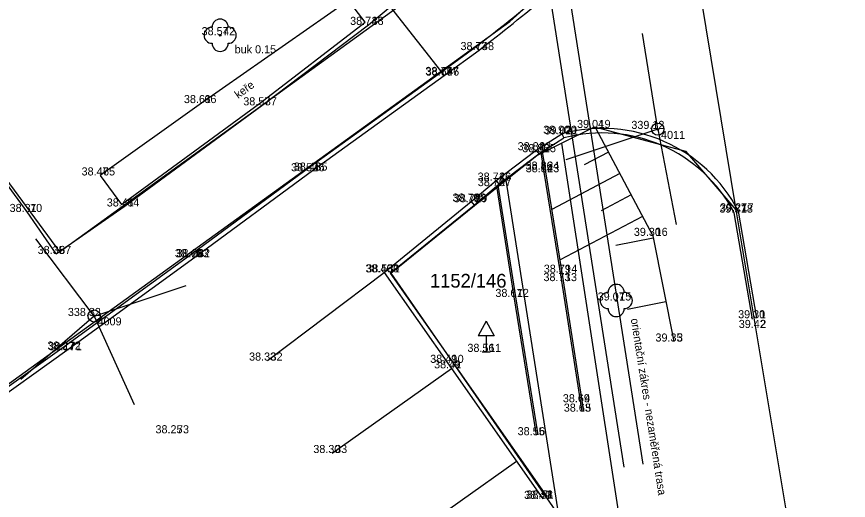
# Model space of a CAD drawing. Extents: x -609709 to -609357, y -1051535 to -1051131.
# Drawn here: x -609522.67 to -609496.91, y -1051331.13 to -1051316.16 of the extents above; entities that cross this region are included whole.
import ezdxf

# ---------------------------------------------------------------- set-up
doc = ezdxf.new("R2010")
doc.units = 0
for name, color, linetype in [('Vrstva 1', 7, 'Continuous'), ('Vrstva 10', 7, 'Continuous'), ('Vrstva 18', 7, 'Continuous'), ('Vrstva 19', 7, 'Continuous'), ('Vrstva 2', 7, 'Continuous'), ('Vrstva 3', 7, 'Continuous'), ('Vrstva 4', 7, 'Continuous'), ('Vrstva 5', 7, 'Continuous'), ('Vrstva 6', 7, 'Continuous'), ('Vrstva 7', 7, 'Continuous'), ('Vrstva 8', 7, 'Continuous')]:
    doc.layers.add(name, color=color, linetype=linetype)

msp = doc.modelspace()

# ---------------------------------------------------------------- linework, layer by layer
at = {"layer": 'Vrstva 1'}
for p, q in [((-609511.77, -1051316.42), (-609511.77, -1051316.42)), ((-609516.37, -1051316.74), (-609516.37, -1051316.74)), ((-609508.35, -1051317.2), (-609508.35, -1051317.2)), ((-609509.44, -1051317.97), (-609509.44, -1051317.97)), ((-609509.43, -1051317.99), (-609509.43, -1051317.99)), ((-609516.95, -1051318.84), (-609516.95, -1051318.84)), ((-609515.08, -1051318.91), (-609515.08, -1051318.91)), ((-609504.74, -1051319.61), (-609504.74, -1051319.61)), ((-609502.81, -1051319.65), (-609502.81, -1051319.65)), ((-609505.78, -1051319.79), (-609505.78, -1051319.79)), ((-609505.75, -1051319.81), (-609505.75, -1051319.81)), ((-609506.58, -1051320.3), (-609506.58, -1051320.3)), ((-609506.43, -1051320.36), (-609506.43, -1051320.36)), ((-609513.6, -1051320.95), (-609513.6, -1051320.95)), ((-609513.51, -1051320.93), (-609513.51, -1051320.93)), ((-609506.33, -1051320.9), (-609506.33, -1051320.9)), ((-609506.33, -1051320.98), (-609506.33, -1051320.98)), ((-609520.09, -1051321.08), (-609520.09, -1051321.08)), ((-609507.82, -1051321.24), (-609507.82, -1051321.24)), ((-609507.81, -1051321.41), (-609507.81, -1051321.41)), ((-609519.34, -1051322.04), (-609519.34, -1051322.04)), ((-609508.59, -1051321.89), (-609508.59, -1051321.89)), ((-609508.56, -1051321.91), (-609508.56, -1051321.91)), ((-609522.35, -1051322.21), (-609522.35, -1051322.21)), ((-609500.33, -1051322.23), (-609500.33, -1051322.23)), ((-609500.31, -1051322.19), (-609500.31, -1051322.19)), ((-609502.97, -1051322.95), (-609502.97, -1051322.95)), ((-609521.45, -1051323.51), (-609521.45, -1051323.51)), ((-609517.19, -1051323.61), (-609517.19, -1051323.61)), ((-609517.15, -1051323.61), (-609517.15, -1051323.61)), ((-609511.29, -1051324.08), (-609511.29, -1051324.08)), ((-609511.27, -1051324.08), (-609511.27, -1051324.08)), ((-609505.77, -1051324.09), (-609505.77, -1051324.09)), ((-609505.78, -1051324.35), (-609505.78, -1051324.35)), ((-609507.27, -1051324.84), (-609507.27, -1051324.84)), ((-609504.1, -1051324.95), (-609504.1, -1051324.95)), ((-609520.27, -1051325.43), (-609520.27, -1051325.43)), ((-609499.74, -1051325.5), (-609499.74, -1051325.5)), ((-609499.73, -1051325.8), (-609499.73, -1051325.8)), ((-609521.15, -1051326.47), (-609521.15, -1051326.47)), ((-609502.31, -1051326.22), (-609502.31, -1051326.22)), ((-609521.12, -1051326.49), (-609521.12, -1051326.49)), ((-609508.13, -1051326.54), (-609508.13, -1051326.54)), ((-609514.9, -1051326.81), (-609514.9, -1051326.81)), ((-609509.29, -1051326.88), (-609509.29, -1051326.88)), ((-609509.2, -1051327.05), (-609509.2, -1051327.05)), ((-609505.18, -1051328.1), (-609505.18, -1051328.1)), ((-609505.15, -1051328.39), (-609505.15, -1051328.39)), ((-609517.8, -1051329.06), (-609517.8, -1051329.06)), ((-609506.58, -1051329.12), (-609506.58, -1051329.12)), ((-609512.9, -1051329.67), (-609512.9, -1051329.67)), ((-609506.37, -1051331.09), (-609506.37, -1051331.09)), ((-609506.34, -1051331.08), (-609506.34, -1051331.08))]:
    msp.add_line(p, q, dxfattribs=at)
at = {"layer": 'Vrstva 10'}
for p, q in [((-609543.54, -1051293.33), (-609521.35, -1051323.44)), ((-609502.54, -1051309.21), (-609500.39, -1051322.14)), ((-609521.35, -1051323.44), (-609508.96, -1051314.48)), ((-609507.4, -1051316.31), (-609506.51, -1051315.51)), ((-609541.54, -1051340.98), (-609507.4, -1051316.31)), ((-609505.79, -1051320.08), (-609504.77, -1051319.58)), ((-609504.77, -1051319.58), (-609501.95, -1051320.33)), ((-609506.56, -1051320.46), (-609505.79, -1051320.08)), ((-609505.79, -1051320.08), (-609495.64, -1051386.18)), ((-609507.52, -1051321.23), (-609506.56, -1051320.46)), ((-609501.95, -1051320.33), (-609500.64, -1051321.85)), ((-609511.08, -1051324.1), (-609507.52, -1051321.23)), ((-609507.52, -1051321.23), (-609505.89, -1051331.59)), ((-609500.64, -1051321.85), (-609500.39, -1051322.14)), ((-609500.39, -1051322.14), (-609491.56, -1051375.22)), ((-609511.08, -1051324.1), (-609505.89, -1051331.59))]:
    msp.add_line(p, q, dxfattribs=at)
at = {"layer": 'Vrstva 18'}
for points in [[(-609502.81, -1051319.65), (-609503.282, -1051316.687)], [(-609502.81, -1051319.65), (-609505.658, -1051320.593)], [(-609502.81, -1051319.65), (-609502.242, -1051322.596)], [(-609520.27, -1051325.43), (-609522.081, -1051323.038)], [(-609520.27, -1051325.43), (-609517.422, -1051324.487)], [(-609520.27, -1051325.43), (-609522.54, -1051327.392)], [(-609520.27, -1051325.43), (-609519.038, -1051328.165)]]:
    msp.add_lwpolyline(points, dxfattribs=at)
for centre, radius in [((-609502.81, -1051319.65), 0.188), ((-609502.81, -1051319.65), 0.025), ((-609520.27, -1051325.43), 0.188), ((-609520.27, -1051325.43), 0.025)]:
    msp.add_circle(centre, radius, dxfattribs=at)
at = {"layer": 'Vrstva 19'}
for points in [[(-609514.503, -1051261.893), (-609510.036, -1051290.33), (-609511.446, -1051290.552), (-609511.003, -1051293.366), (-609509.669, -1051293.157), (-609503.864, -1051330.113)], [(-609513.91, -1051261.8), (-609509.35, -1051290.83), (-609510.76, -1051291.051), (-609510.504, -1051292.681), (-609509.17, -1051292.471), (-609503.272, -1051330.02)]]:
    msp.add_lwpolyline(points, dxfattribs=at)
at = {"layer": 'Vrstva 4'}
for p, q in [((-609509.513, -1051317.877), (-609508.434, -1051317.088)), ((-609513.592, -1051320.817), (-609509.512, -1051317.876)), ((-609517.233, -1051323.497), (-609513.592, -1051320.817)), ((-609499.878, -1051325.524), (-609500.444, -1051322.235)), ((-609521.202, -1051326.376), (-609517.233, -1051323.497)), ((-609511.1, -1051324.106), (-609509.086, -1051326.969)), ((-609523.801, -1051328.226), (-609521.202, -1051326.376)), ((-609509.085, -1051326.97), (-609506.255, -1051331.01))]:
    msp.add_line(p, q, dxfattribs=at)
for points in [[(-609521.45, -1051323.51), (-609522.35, -1051322.21), (-609525.21, -1051318.31), (-609528.01, -1051314.48), (-609531.78, -1051309.4), (-609534.64, -1051305.47), (-609537.5, -1051301.63), (-609539.35, -1051299.05), (-609542.53, -1051294.7), (-609543.53, -1051293.34), (-609542.23, -1051292.32), (-609542.49, -1051291.97)], [(-609567.69, -1051305.73), (-609565.19, -1051309.21), (-609561.45, -1051314.29), (-609556.48, -1051321.05), (-609552.89, -1051325.9), (-609549.26, -1051330.78), (-609545.88, -1051335.35), (-609541.56, -1051341.2), (-609537.96, -1051338.59), (-609534.58, -1051336.17), (-609530.96, -1051333.54), (-609527.42, -1051330.97), (-609523.72, -1051328.34), (-609521.12, -1051326.49), (-609517.15, -1051323.61), (-609513.51, -1051320.93), (-609509.43, -1051317.99)], [(-609521.45, -1051323.51), (-609519.34, -1051322.04), (-609515.08, -1051318.91), (-609511.77, -1051316.42), (-609511.1, -1051315.86), (-609509.43, -1051317.99)], [(-609508.35, -1051317.2), (-609508.434, -1051317.088)], [(-609509.43, -1051317.99), (-609508.35, -1051317.2)], [(-609511.29, -1051324.08), (-609508.59, -1051321.89), (-609507.82, -1051321.24), (-609506.58, -1051320.3), (-609505.78, -1051319.79)], [(-609511.1, -1051324.106), (-609508.501, -1051321.998), (-609507.732, -1051321.349), (-609506.5, -1051320.415), (-609505.723, -1051319.92)], [(-609505.78, -1051319.79), (-609505.723, -1051319.92)], [(-609506.58, -1051320.3), (-609506.5, -1051320.415)], [(-609505.15, -1051328.39), (-609505.78, -1051324.35), (-609506.33, -1051320.98), (-609506.428, -1051320.369)], [(-609505.101, -1051328.382), (-609505.731, -1051324.342), (-609506.281, -1051320.972), (-609506.383, -1051320.34)], [(-609507.82, -1051321.24), (-609507.732, -1051321.349)], [(-609507.809, -1051321.414), (-609507.27, -1051324.84), (-609506.58, -1051329.12)], [(-609507.765, -1051321.376), (-609507.221, -1051324.832), (-609506.531, -1051329.112)], [(-609508.59, -1051321.89), (-609508.501, -1051321.998)], [(-609499.74, -1051325.5), (-609500.31, -1051322.19)], [(-609514.9, -1051326.81), (-609511.29, -1051324.08)], [(-609511.29, -1051324.08), (-609509.2, -1051327.05)], [(-609512.9, -1051329.67), (-609509.2, -1051327.05)], [(-609509.2, -1051327.05), (-609506.37, -1051331.09)], [(-609510.68, -1051332.4), (-609507.186, -1051329.926)]]:
    msp.add_lwpolyline(points, dxfattribs=at)
for centre, radius, start, end in [((-609539.416, -1051276.412), 51.131, 307.2963, 310.2906), ((-609539.416, -1051276.412), 51.271, 307.2948, 310.2918), ((-609504.534, -1051324.384), 4.76, 27.4507, 105.1697), ((-609504.534, -1051324.384), 4.62, 27.7188, 104.9068)]:
    msp.add_arc(centre, radius, start, end, dxfattribs=at)
at = {"layer": 'Vrstva 5'}
for p, q in [((-609508.13, -1051325.59), (-609508.38, -1051326.04)), ((-609508.13, -1051325.59), (-609507.88, -1051326.04)), ((-609507.88, -1051326.04), (-609508.38, -1051326.04)), ((-609508.13, -1051326.04), (-609508.13, -1051326.54)), ((-609508.255, -1051326.54), (-609508.005, -1051326.54))]:
    msp.add_line(p, q, dxfattribs=at)
at = {"layer": 'Vrstva 6'}
msp.add_lwpolyline([(-609504.74, -1051319.61), (-609502.97, -1051322.95), (-609502.31, -1051326.22)], dxfattribs=at)
at = {"layer": 'Vrstva 7'}
msp.add_lwpolyline([(-609512.39, -1051315.66), (-609516.95, -1051318.84), (-609520.09, -1051321.08), (-609519.43, -1051321.98), (-609515.15, -1051318.85), (-609511.88, -1051316.34), (-609512.39, -1051315.66)], dxfattribs=at)
for centre in [(-609516.37, -1051316.74), (-609504.1, -1051324.95)]:
    msp.add_circle(centre, 0.025, dxfattribs=at)
for centre, start, end in [((-609516.37, -1051316.49), 0, 180), ((-609516.62, -1051316.74), 90, 270), ((-609516.12, -1051316.74), 270, 90), ((-609516.37, -1051316.99), 180, 0), ((-609504.1, -1051324.7), 0, 180), ((-609504.35, -1051324.95), 90, 270), ((-609503.85, -1051324.95), 270, 90), ((-609504.1, -1051325.2), 180, 0)]:
    msp.add_arc(centre, 0.25, start, end, dxfattribs=at)
at = {"layer": 'Vrstva 8'}
for p, q in [((-609504.343, -1051320.358), (-609505.093, -1051320.756)), ((-609503.992, -1051321.021), (-609506.091, -1051322.133)), ((-609503.641, -1051321.684), (-609504.57, -1051322.176)), ((-609503.29, -1051322.346), (-609505.836, -1051323.696)), ((-609502.957, -1051323.016), (-609504.115, -1051323.249)), ((-609502.559, -1051324.986), (-609503.75, -1051325.226))]:
    msp.add_line(p, q, dxfattribs=at)

# ---------------------------------------------------------------- texts
at = {"layer": 'Vrstva 10'}
msp.add_text('1152/146', height=0.425, dxfattribs=at).set_placement((-609509.87, -1051324.551))
at = {"layer": 'Vrstva 18'}
for s, p in [(' 4011', (-609502.803, -1051319.95)), (' 4009', (-609520.26, -1051325.72))]:
    msp.add_text(s, height=0.25, dxfattribs=at).set_placement(p)
at = {"layer": 'Vrstva 19'}
msp.add_text('orientační zákres - nezaměřená trasa', height=0.25, rotation=278.927, dxfattribs=at).set_placement((-609503.65, -1051325.52))
at = {"layer": 'Vrstva 2'}
for s, p in [(' 38', (-609511.77, -1051316.42)), (' 42', (-609516.37, -1051316.74)), (' 48', (-609508.35, -1051317.2)), (' 47', (-609509.44, -1051317.97)), (' 46', (-609509.43, -1051317.99)), (' 66', (-609516.95, -1051318.84)), (' 37', (-609515.08, -1051318.91)), (' 19', (-609504.74, -1051319.61)), (' 20', (-609505.78, -1051319.79)), (' 21', (-609505.75, -1051319.81)), (' 22', (-609506.58, -1051320.3)), (' 25', (-609506.43, -1051320.36)), (' 36', (-609513.6, -1051320.95)), (' 35', (-609513.51, -1051320.93)), (' 24', (-609506.33, -1051320.9)), (' 23', (-609506.33, -1051320.98)), (' 65', (-609520.09, -1051321.08)), (' 26', (-609507.82, -1051321.24)), (' 27', (-609507.81, -1051321.41)), (' 64', (-609519.34, -1051322.04)), (' 28', (-609508.59, -1051321.89)), (' 29', (-609508.56, -1051321.91)), (' 70', (-609522.35, -1051322.21)), (' 18', (-609500.33, -1051322.23)), (' 17', (-609500.31, -1051322.19)), (' 16', (-609502.97, -1051322.95)), (' 67', (-609521.45, -1051323.51)), (' 63', (-609517.19, -1051323.61)), (' 62', (-609517.15, -1051323.61)), (' 30', (-609511.29, -1051324.08)), (' 31', (-609511.27, -1051324.08)), (' 14', (-609505.77, -1051324.09)), (' 13', (-609505.78, -1051324.35)), (' 12', (-609507.27, -1051324.84)), (' 15', (-609504.1, -1051324.95)), (' 1', (-609499.74, -1051325.5)), (' 2', (-609499.73, -1051325.8)), (' 72', (-609521.15, -1051326.47)), (' 3', (-609502.31, -1051326.22)), (' 71', (-609521.12, -1051326.49)), (' 11', (-609508.13, -1051326.54)), (' 32', (-609514.9, -1051326.81)), (' 10', (-609509.29, -1051326.88)), (' 9', (-609509.2, -1051327.05)), (' 4', (-609505.18, -1051328.1)), (' 5', (-609505.15, -1051328.39)), (' 73', (-609517.8, -1051329.06)), (' 6', (-609506.58, -1051329.12)), (' 33', (-609512.9, -1051329.67)), (' 7', (-609506.37, -1051331.09)), (' 8', (-609506.34, -1051331.08))]:
    msp.add_text(s, height=0.25, dxfattribs=at).set_placement(p)
at = {"layer": 'Vrstva 3'}
for s, p in [('38.74', (-609512.343, -1051316.42)), ('38.57', (-609516.943, -1051316.74)), ('38.73', (-609508.923, -1051317.2)), ('38.77', (-609510.013, -1051317.97)), ('38.69', (-609510.003, -1051317.99)), ('38.61', (-609517.492, -1051318.84)), ('38.57', (-609515.653, -1051318.91)), ('39.04', (-609505.313, -1051319.61)), ('339.12', (-609503.63, -1051319.64)), ('38.90', (-609506.363, -1051319.79)), ('39.02', (-609506.323, -1051319.81)), ('38.84', (-609507.153, -1051320.3)), ('38.86', (-609507.009, -1051320.36)), ('38.52', (-609514.173, -1051320.95)), ('38.46', (-609514.089, -1051320.93)), ('38.86', (-609506.909, -1051320.9)), ('38.84', (-609506.903, -1051320.98)), ('38.47', (-609520.663, -1051321.08)), ('38.74', (-609508.393, -1051321.24)), ('38.76', (-609508.389, -1051321.41)), ('38.41', (-609519.882, -1051322.04)), ('38.70', (-609509.173, -1051321.89)), ('38.79', (-609509.133, -1051321.91)), ('38.31', (-609522.892, -1051322.21)), ('39.37', (-609500.903, -1051322.23)), ('39.27', (-609500.883, -1051322.19)), ('39.30', (-609503.553, -1051322.95)), ('38.35', (-609522.023, -1051323.51)), ('38.40', (-609517.773, -1051323.61)), ('38.28', (-609517.723, -1051323.61)), ('38.46', (-609511.869, -1051324.08)), ('38.53', (-609511.843, -1051324.08)), ('38.79', (-609506.343, -1051324.09)), ('38.73', (-609506.353, -1051324.35)), ('38.67', (-609507.843, -1051324.84)), ('39.07', (-609504.673, -1051324.95)), ('338.32', (-609521.088, -1051325.43)), ('39.30', (-609500.323, -1051325.5)), ('39.42', (-609500.303, -1051325.8)), ('38.27', (-609521.723, -1051326.47)), ('39.35', (-609502.883, -1051326.22)), ('38.17', (-609521.693, -1051326.49)), ('38.56', (-609508.709, -1051326.54)), ('38.33', (-609515.473, -1051326.81)), ('38.49', (-609509.863, -1051326.88)), ('38.41', (-609509.742, -1051327.05)), ('38.69', (-609505.753, -1051328.1)), ('38.63', (-609505.723, -1051328.39)), ('38.25', (-609518.373, -1051329.06)), ('38.55', (-609507.153, -1051329.12)), ('38.30', (-609513.483, -1051329.67)), ('38.40', (-609506.953, -1051331.09)), ('38.51', (-609506.882, -1051331.08))]:
    msp.add_text(s, height=0.25, dxfattribs=at).set_placement(p)
at = {"layer": 'Vrstva 7'}
msp.add_text('buk 0.15', height=0.25, dxfattribs=at).set_placement((-609515.92, -1051317.3))
msp.add_text('keře', height=0.25, rotation=36.1783, dxfattribs=at).set_placement((-609515.81, -1051318.713))

doc.saveas('drawing.dxf')
